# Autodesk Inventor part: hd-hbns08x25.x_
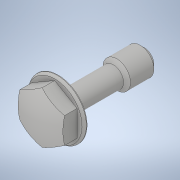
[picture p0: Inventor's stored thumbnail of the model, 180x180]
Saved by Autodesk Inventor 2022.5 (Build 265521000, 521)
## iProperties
Created: 2021-02
Part Number: hd-hbns08x25.x_
Material: 一般
Document SubType Name: Modeling
Designer: ImaoCorp
Density: 1 g/cm^3
Appearance: 既定
Sending System: SOLIDWORKS 2019-2019304
MC: AMD64
MC_MODEL: Intel64 Family 6 Model 60 Stepping 3, GenuineIntel
OS: Windows_NT
FRU: Parasolid Version 31.0, build 290,  9- 1-2019
FORMAT: text
GUISE: transmit
KEY: hd-hbns08x25
FILE: hd-hbns08x25.x_t
DATE: Mon Feb 22 15:00:56 2021
Author: ImaoCorp
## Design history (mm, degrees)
feature "Base1"
node "ソリッド1"
